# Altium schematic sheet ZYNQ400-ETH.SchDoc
size A3
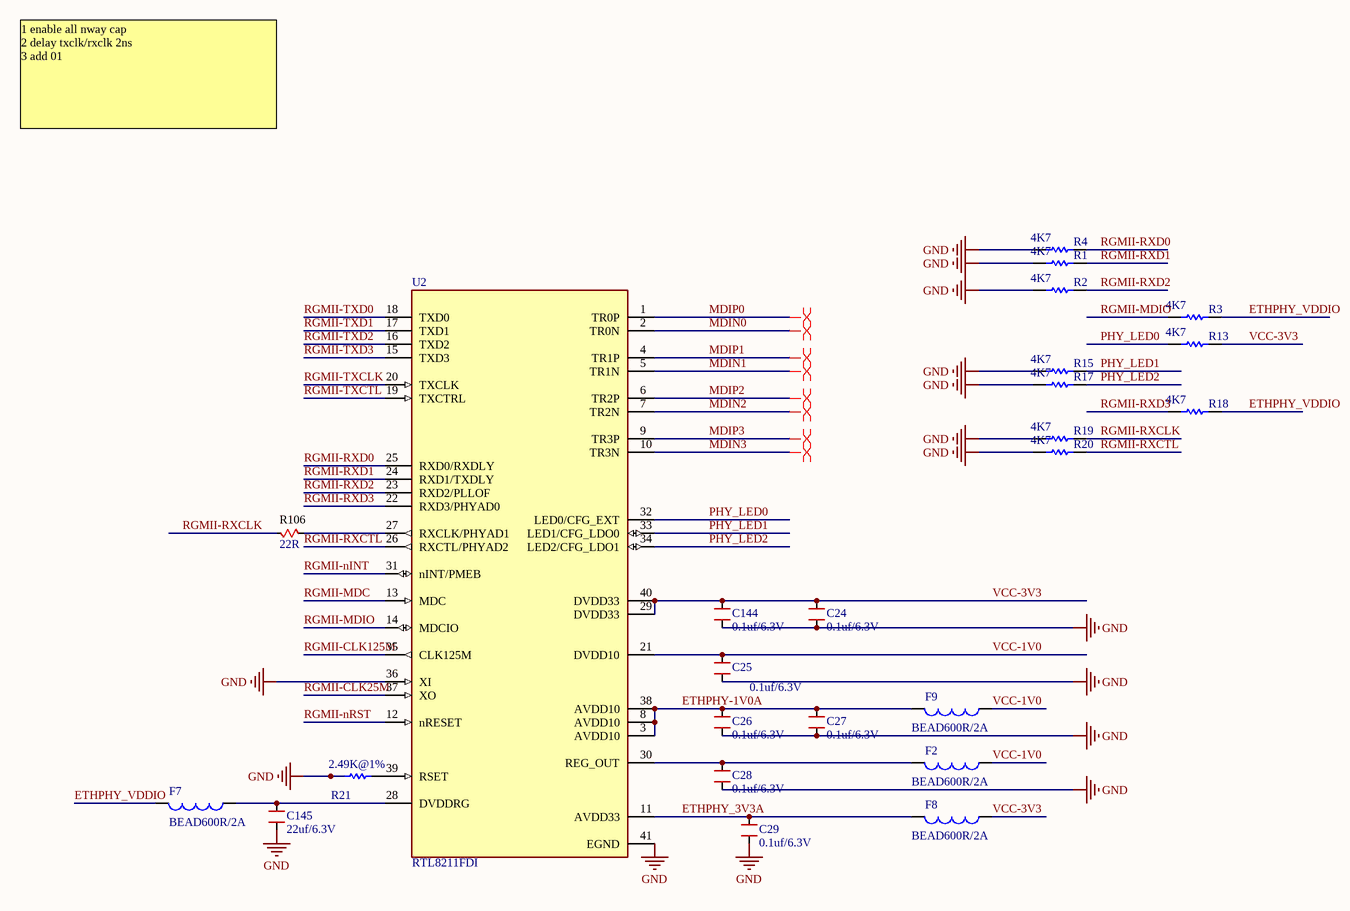
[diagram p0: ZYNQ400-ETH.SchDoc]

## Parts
C24  0.1uf/6.3V  [0402]
C25  0.1uf/6.3V  [0402]
C26  0.1uf/6.3V  [0402]
C27  0.1uf/6.3V  [0402]
C28  0.1uf/6.3V  [0402]
C29  0.1uf/6.3V  [0402]
C144  0.1uf/6.3V  [0402]
C145  22uf/6.3V  [0603]
F2  BEAD600R/2A  [0603]
F7  BEAD600R/2A  [0603]
F8  BEAD600R/2A  [0603]
F9  BEAD600R/2A  [0603]
R1  4K7  [0402]
R2  4K7  [0402]
R3  4K7  [0402]
R4  4K7  [0402]
R13  4K7  [0402]
R15  4K7  [0402]
R17  4K7  [0402]
R18  4K7  [0402]
R19  4K7  [0402]
R20  4K7  [0402]
R21  2.49K@1%  [0402]
R106  22R  [0402]
U2  RTL8211FDI  [QFN40]

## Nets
GND: C24.1 C25.1 C26.1 C27.1 C28.1 C29.1 C144.1 C145.1 R1.2 R2.2 R4.2 R15.2 R17.2 R19.2 R20.2 R21.2 U2.36(XI) U2.41(EGND)
ETHPHY-1V0A: C26.2 C27.2 F9.2 U2.3(AVDD10) U2.8(AVDD10) U2.38(AVDD10)
ETHPHY_3V3A: C29.2 F8.2 U2.11(AVDD33)
ETHPHY_VDDIO: F7.2 R3.1 R18.1
MDIN0: U2.2(TR0N)
MDIN1: U2.5(TR1N)
MDIN2: U2.7(TR2N)
MDIN3: U2.10(TR3N)
MDIP0: U2.1(TR0P)
MDIP1: U2.4(TR1P)
MDIP2: U2.6(TR2P)
MDIP3: U2.9(TR3P)
PHY_LED0: R13.2 U2.32(LED0/CFG_EXT)
PHY_LED1: R15.1 U2.33(LED1/CFG_LDO0)
PHY_LED2: R17.1 U2.34(LED2/CFG_LDO1)
RGMII-CLK25M: U2.37(XO)
RGMII-CLK125M: U2.35(CLK125M)
RGMII-MDC: U2.13(MDC)
RGMII-MDIO: R3.2 U2.14(MDCIO)
RGMII-nINT: U2.31(nINT/PMEB)
RGMII-nRST: U2.12(nRESET)
RGMII-RXCLK: R19.1 R106.1
RGMII-RXCTL: R20.1 U2.26(RXCTL/PHYAD2)
RGMII-RXD0: R4.1 U2.25(RXD0/RXDLY)
RGMII-RXD1: R1.1 U2.24(RXD1/TXDLY)
RGMII-RXD2: R2.1 U2.23(RXD2/PLLOF)
RGMII-RXD3: R18.2 U2.22(RXD3/PHYAD0)
RGMII-TXCLK: U2.20(TXCLK)
RGMII-TXCTL: U2.19(TXCTRL)
RGMII-TXD0: U2.18(TXD0)
RGMII-TXD1: U2.17(TXD1)
RGMII-TXD2: U2.16(TXD2)
RGMII-TXD3: U2.15(TXD3)
VCC-1V0: C25.2 F2.1 F9.1 U2.21(DVDD10)
VCC-3V3: C24.2 C144.2 F8.1 R13.1 U2.29(DVDD33) U2.40(DVDD33)
NetC28_2: C28.2 F2.2 U2.30(REG_OUT)
NetC145_2: C145.2 F7.1 U2.28(DVDDRG)
NetR21_1: R21.1 U2.39(RSET)
NetR106_2: R106.2 U2.27(RXCLK/PHYAD1)

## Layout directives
differential pair: MDIN0, MDIN1, MDIN2, MDIN3, MDIP0, MDIP1, MDIP2, MDIP3

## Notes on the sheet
- 1 enable all nway cap
  2 delay txclk/rxclk 2ns
  3 add 01

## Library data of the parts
C24-C29 C144 C145 = CAPACITOR: Generic Capacitor
F2 F7-F9 = Inductor: Code_IEC: 1005
R1-R4 R13 R15 R17-R21 = Res1: Resistor; Value: 12.1K
R106 = RESISTOR: Generic Resistor; Value: 1K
